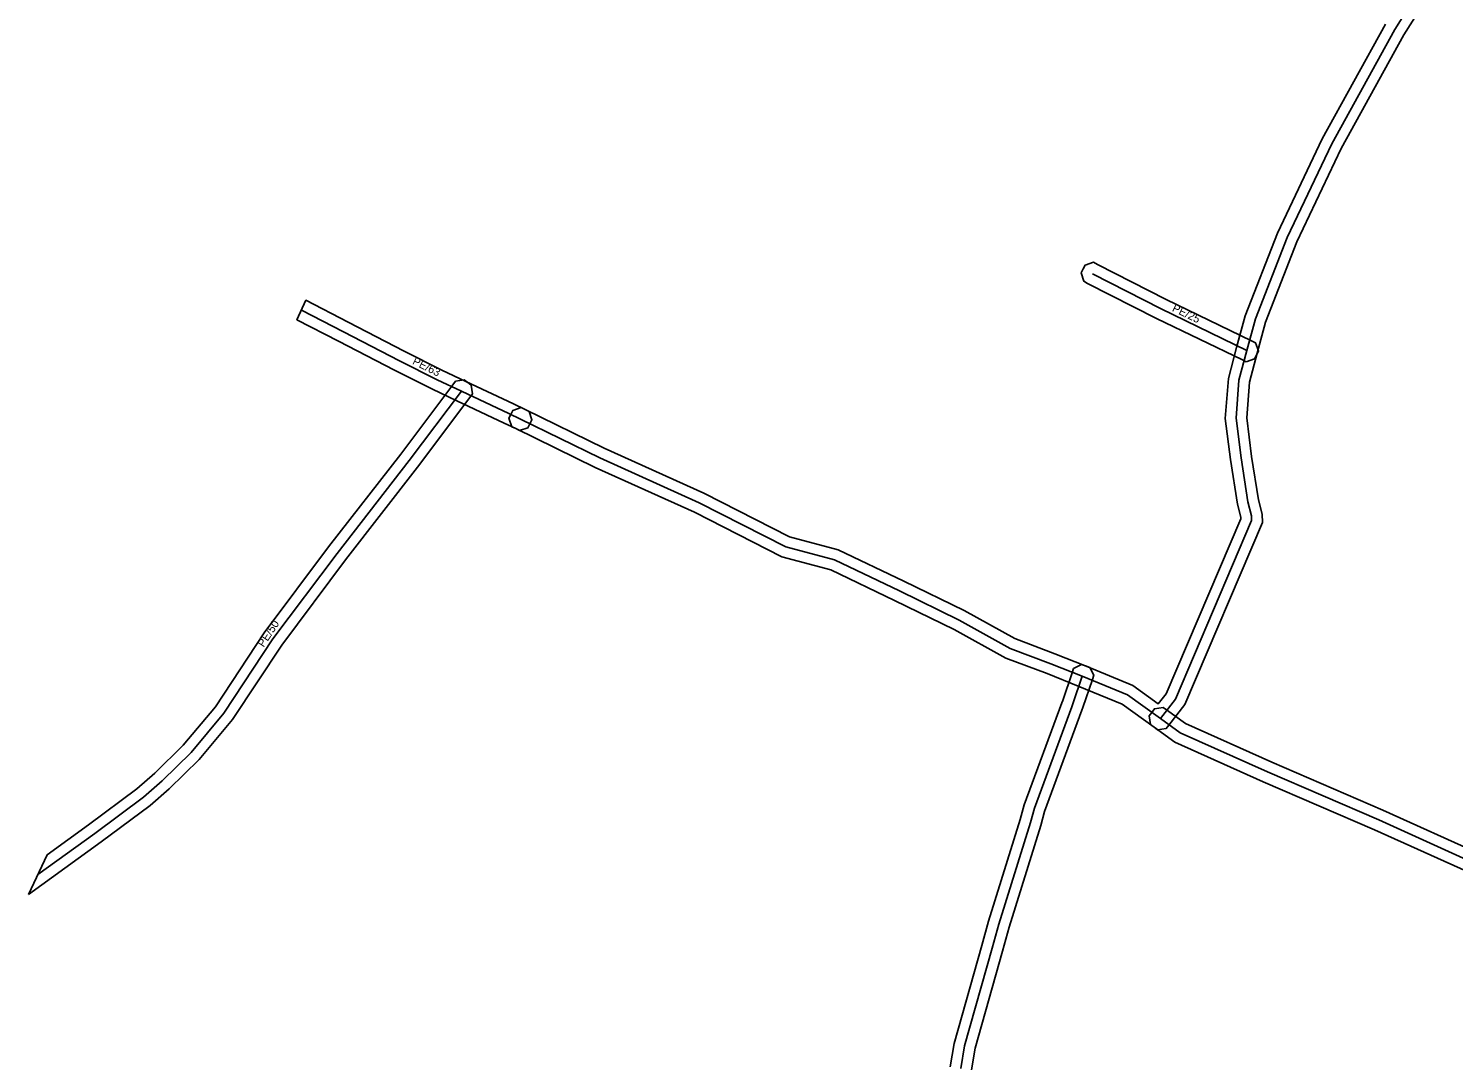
# Model space of a CAD drawing. Extents: x -681050 to -680828, y -1057939 to -1057551.
# Drawn here: x -681050.2 to -680916.7, y -1057842.3 to -1057745.3 of the extents above; entities that cross this region are included whole.
import ezdxf

# ---------------------------------------------------------------- set-up
doc = ezdxf.new("R2010")
doc.units = 0
for name, color, linetype in [('1', 7, 'Continuous'), ('24', 7, 'Continuous'), ('30', 7, 'Continuous')]:
    doc.layers.add(name, color=color, linetype=linetype)

msp = doc.modelspace()

# ---------------------------------------------------------------- linework, layer by layer
at = {"layer": '1'}
for points in [[(-680918.89, -1057742.03), (-680921.3, -1057745.93), (-680927.18, -1057756.58), (-680931.33, -1057765.31), (-680934.28, -1057772.86), (-680935.05, -1057775.75), (-680935.78, -1057778.46), (-680936.04, -1057781.83), (-680935.58, -1057785.43), (-680934.95, -1057789.5), (-680934.6, -1057790.84), (-680934.57, -1057791.63), (-680941.85, -1057808.69), (-680943.34, -1057810.61), (-680943.59, -1057810.93), (-680944.39, -1057811.05), (-680944.71, -1057810.81), (-680947.71, -1057808.65), (-680951.83, -1057806.95), (-680954.75, -1057805.79), (-680958.62, -1057804.33), (-680963.46, -1057801.66), (-680969.04, -1057798.93), (-680975.03, -1057796.07), (-680979.61, -1057794.84), (-680987.8, -1057790.67), (-680997.1, -1057786.48), (-681004.56, -1057782.83), (-681004.93, -1057782.65), (-681005.2, -1057781.86), (-681005.02, -1057781.49), (-681004.84, -1057781.12), (-681004.05, -1057780.85), (-681003.68, -1057781.03), (-680996.26, -1057784.67), (-680986.94, -1057788.87), (-680978.89, -1057792.96), (-680974.33, -1057794.19), (-680968.17, -1057797.13), (-680962.54, -1057799.88), (-680957.78, -1057802.51), (-680954.03, -1057803.93), (-680951.08, -1057805.09), (-680946.73, -1057806.89), (-680944.33, -1057808.62), (-680943.59, -1057807.67), (-680936.59, -1057791.27), (-680936.59, -1057791.14), (-680936.91, -1057789.9), (-680937.56, -1057785.71), (-680938.05, -1057781.89), (-680937.76, -1057778.12), (-680936.99, -1057775.23), (-680936.18, -1057772.24), (-680933.17, -1057764.51), (-680928.96, -1057755.66), (-680923.02, -1057744.92)], [(-680963.83, -1057842.65), (-680963.46, -1057840.46), (-680960.86, -1057831.26), (-680960.24, -1057828.98), (-680957.27, -1057819.47), (-680956.89, -1057818.1), (-680953.36, -1057808.54), (-680953.27, -1057808.3), (-680952.41, -1057805.7), (-680952.28, -1057805.31), (-680951.54, -1057804.94), (-680951.14, -1057805.07), (-680950.75, -1057805.2), (-680950.38, -1057805.94), (-680950.51, -1057806.34), (-680951.39, -1057808.96), (-680951.49, -1057809.23), (-680954.99, -1057818.72), (-680955.35, -1057820.03), (-680958.32, -1057829.54), (-680958.94, -1057831.8), (-680961.5, -1057840.9), (-680961.85, -1057842.93)], [(-680914.75, -1057824.63), (-680924.07, -1057820.42), (-680934.5, -1057815.92), (-680942.78, -1057812.2), (-680944.71, -1057810.81), (-680945.05, -1057810.57), (-680945.18, -1057809.75), (-680944.94, -1057809.42), (-680944.7, -1057809.08), (-680943.88, -1057808.95), (-680943.55, -1057809.19), (-680941.78, -1057810.46), (-680933.7, -1057814.08), (-680923.27, -1057818.58), (-680913.99, -1057822.77)]]:
    msp.add_lwpolyline(points, dxfattribs=at)
for points in [[(-680936.08, -1057776.57), (-680936.45, -1057776.39), (-680944.49, -1057772.51), (-680950.95, -1057769.21), (-680951.31, -1057769.02), (-680951.57, -1057768.23), (-680951.38, -1057767.86), (-680951.19, -1057767.5), (-680950.4, -1057767.24), (-680950.04, -1057767.43), (-680943.6, -1057770.71), (-680935.58, -1057774.59), (-680935.21, -1057774.77), (-680934.94, -1057775.55), (-680935.12, -1057775.93), (-680935.3, -1057776.3)], [(-681021.17, -1057774.64), (-681025.07, -1057772.62), (-681024.22, -1057770.8), (-681020.25, -1057772.86), (-681015.01, -1057775.57), (-681011.47, -1057777.34), (-681009.22, -1057778.41), (-681004.77, -1057780.5), (-681003.68, -1057781.03), (-681003.31, -1057781.22), (-681003.04, -1057782), (-681003.22, -1057782.37), (-681003.41, -1057782.74), (-681004.19, -1057783.01), (-681004.56, -1057782.83), (-681005.63, -1057782.3), (-681010.08, -1057780.21), (-681012.35, -1057779.14), (-681015.91, -1057777.35)], [(-681050.23, -1057826.5), (-681048.48, -1057822.77), (-681044.6, -1057819.95), (-681040.08, -1057816.59), (-681038.39, -1057815.12), (-681035.72, -1057812.49), (-681032.71, -1057808.9), (-681028.13, -1057801.96), (-681022.1, -1057793.91), (-681015.34, -1057785.21), (-681010.45, -1057778.71), (-681010.2, -1057778.38), (-681009.38, -1057778.26), (-681009.05, -1057778.51), (-681008.72, -1057778.76), (-681008.6, -1057779.58), (-681008.85, -1057779.91), (-681013.76, -1057786.43), (-681020.52, -1057795.13), (-681026.49, -1057803.12), (-681031.11, -1057810.1), (-681034.24, -1057813.85), (-681037.03, -1057816.58), (-681038.82, -1057818.15), (-681043.42, -1057821.57)]]:
    msp.add_lwpolyline(points, close=True, dxfattribs=at)
at = {"layer": '24'}
for points in [[(-680919.76, -1057741.54), (-680922.16, -1057745.42), (-680928.07, -1057756.12), (-680932.25, -1057764.91), (-680935.23, -1057772.55), (-680936.02, -1057775.49), (-680936.77, -1057778.29), (-680937.04, -1057781.86), (-680936.57, -1057785.57), (-680935.93, -1057789.7), (-680935.6, -1057790.99), (-680935.58, -1057791.45), (-680942.72, -1057808.18), (-680944.13, -1057810), (-680947.22, -1057807.77), (-680951.46, -1057806.02), (-680954.39, -1057804.86), (-680958.2, -1057803.42), (-680963, -1057800.77), (-680968.6, -1057798.03), (-680974.68, -1057795.13), (-680979.25, -1057793.9), (-680987.37, -1057789.77), (-680996.68, -1057785.57), (-681004.12, -1057781.93)], [(-680936.02, -1057775.49), (-680944.05, -1057771.61), (-680950.49, -1057768.32)], [(-681004.12, -1057781.93), (-681005.2, -1057781.4), (-681009.65, -1057779.31), (-681011.91, -1057778.24), (-681015.46, -1057776.46), (-681020.71, -1057773.75), (-681024.64, -1057771.71)], [(-681009.65, -1057779.31), (-681014.55, -1057785.82), (-681021.31, -1057794.52), (-681027.31, -1057802.54), (-681031.91, -1057809.5), (-681034.98, -1057813.17), (-681037.71, -1057815.85), (-681039.45, -1057817.37), (-681044.01, -1057820.76), (-681049.35, -1057824.63)], [(-680951.46, -1057806.02), (-680952.33, -1057808.63), (-680952.43, -1057808.89), (-680955.94, -1057818.41), (-680956.31, -1057819.75), (-680959.28, -1057829.26), (-680959.9, -1057831.53), (-680962.48, -1057840.68), (-680962.84, -1057842.79)], [(-680914.37, -1057823.7), (-680923.67, -1057819.5), (-680934.1, -1057815), (-680942.28, -1057811.33), (-680944.13, -1057810)]]:
    msp.add_lwpolyline(points, dxfattribs=at)

# ---------------------------------------------------------------- texts
at = {"layer": '30'}
for s, rotation, p in [('PE/25', 334.2107, (-680943.09, -1057771.78)), ('PE/63', 333.3704, (-681014.3, -1057776.74)), ('PE/50', 56.5385, (-681028.19, -1057803.37))]:
    msp.add_text(s, height=0.75, rotation=rotation, dxfattribs=at).set_placement(p)

doc.saveas('drawing.dxf')
